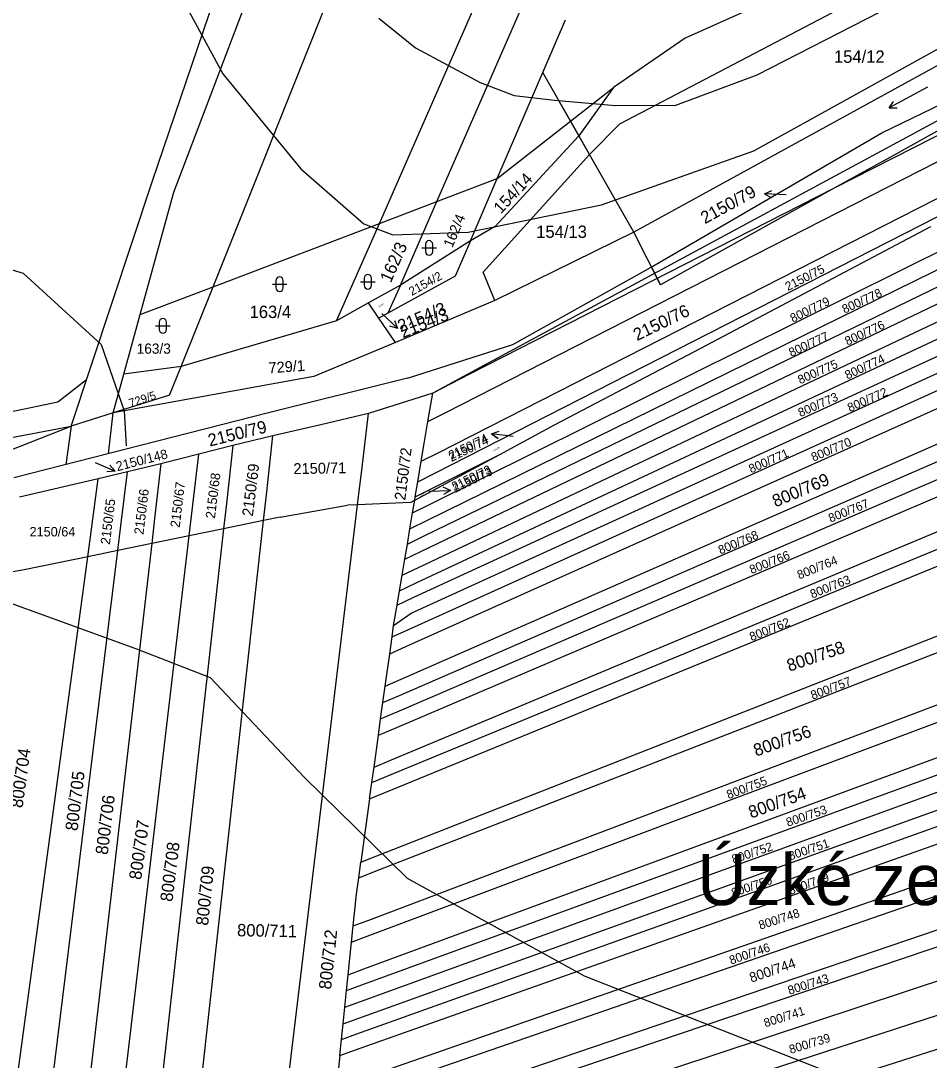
# Model space of a CAD drawing. Extents: x -555860 to -552701, y -1187050 to -1182291.
# Drawn here: x -554861.7 to -554737.1, y -1185587.5 to -1185444.8 of the extents above; entities that cross this region are included whole.
import ezdxf

# ---------------------------------------------------------------- set-up
doc = ezdxf.new("R2010")
doc.units = 0
for name, color, linetype in [('LEG_2b', 7, 'Continuous'), ('Level 16', 7, 'Continuous'), ('Level 25', 7, 'Continuous'), ('Level 32', 7, 'Continuous'), ('Level 40', 7, 'Continuous'), ('Level 41', 7, 'Continuous'), ('navrh_BV', 7, 'Continuous'), ('Parcelní čísla', 7, 'Continuous'), ('Poz předměty', 7, 'Continuous'), ('stav_BV', 7, 'Continuous')]:
    doc.layers.add(name, color=color, linetype=linetype)

msp = doc.modelspace()

# ---------------------------------------------------------------- linework, layer by layer
at = {"layer": 'Level 16'}
for p, q in [((-554759.67, -1185468.55), (-554758.65, -1185468.09)), ((-554756.67, -1185468.68), (-554759.67, -1185468.55)), ((-554759.67, -1185468.55), (-554758.69, -1185469.09)), ((-554812.17, -1185484.98), (-554809.97, -1185487.02)), ((-554809.97, -1185487.02), (-554810.36, -1185485.97)), ((-554809.97, -1185487.02), (-554811.04, -1185486.71)), ((-554797.1, -1185501.49), (-554796.05, -1185501.1)), ((-554794.12, -1185501.83), (-554797.1, -1185501.49)), ((-554797.1, -1185501.49), (-554796.17, -1185502.1)), ((-554851.5, -1185505.42), (-554848.75, -1185506.62)), ((-554848.75, -1185506.62), (-554849.86, -1185506.68)), ((-554848.75, -1185506.62), (-554849.47, -1185505.76)), ((-554805.71, -1185509.35), (-554802.71, -1185509.25)), ((-554802.71, -1185509.25), (-554803.73, -1185508.78)), ((-554802.71, -1185509.25), (-554803.69, -1185509.78))]:
    msp.add_line(p, q, dxfattribs=at)
at = {"layer": 'Level 25'}
for p, q in [((-554737.28, -1185453.91), (-554742.56, -1185456.75)), ((-554742.56, -1185456.75), (-554741.94, -1185455.85)), ((-554742.56, -1185456.75), (-554741.46, -1185456.73)), ((-554806.67, -1185475.96), (-554804.67, -1185475.96)), ((-554806.17, -1185475.46), (-554806.17, -1185476.46)), ((-554805.17, -1185476.46), (-554805.17, -1185475.46)), ((-554827.17, -1185480.93), (-554825.17, -1185480.93)), ((-554826.67, -1185480.43), (-554826.67, -1185481.43)), ((-554825.67, -1185481.43), (-554825.67, -1185480.43)), ((-554815.08, -1185480.6), (-554813.08, -1185480.6)), ((-554814.58, -1185480.1), (-554814.58, -1185481.1)), ((-554813.58, -1185481.1), (-554813.58, -1185480.1)), ((-554843.2, -1185486.65), (-554841.2, -1185486.65)), ((-554842.7, -1185486.15), (-554842.7, -1185487.15)), ((-554841.7, -1185487.15), (-554841.7, -1185486.15))]:
    msp.add_line(p, q, dxfattribs=at)
for centre, start, end in [((-554805.67, -1185475.46), 0, 180), ((-554805.67, -1185476.46), 180, 359.9879), ((-554826.17, -1185480.43), 0, 180), ((-554814.08, -1185480.1), 0, 180), ((-554826.17, -1185481.43), 180, 359.9879), ((-554814.08, -1185481.1), 180, 359.9879), ((-554842.2, -1185486.15), 0, 180), ((-554842.2, -1185487.15), 180, 359.9879)]:
    msp.add_arc(centre, 0.5, start, end, dxfattribs=at)
at = {"layer": 'Level 32'}
msp.add_lwpolyline([(-554698.05, -1185438.6), (-554714.96, -1185448.24), (-554741.93, -1185463.25), (-554750.17, -1185467.82), (-554773.94, -1185481.01), (-554777.58, -1185473.79), (-554783.65, -1185463.15), (-554790.07, -1185451.89), (-554786.97, -1185444.66)], dxfattribs=at)
at = {"layer": 'Level 40'}
msp.add_lwpolyline([(-554812.57, -1185444.44), (-554807.55, -1185448.5), (-554798.66, -1185453.23), (-554793.98, -1185455.02), (-554788.44, -1185455.68), (-554780.08, -1185456.4), (-554771.8, -1185456.38), (-554760.66, -1185452.22), (-554741.91, -1185442.57)], dxfattribs=at)
at = {"layer": 'Level 41'}
for points in [[(-554871.41, -1185304.71), (-554871.04, -1185319.22), (-554873.45, -1185336.56), (-554879.64, -1185354.6), (-554880.53, -1185368.5), (-554877.6, -1185382.58), (-554873.3, -1185396.32), (-554862.7, -1185410.01), (-554853.22, -1185420.99), (-554839.21, -1185442.35), (-554833.95, -1185452.05), (-554823.27, -1185465.09), (-554814.61, -1185472.65), (-554810.64, -1185474.15), (-554800.31, -1185473.8), (-554782, -1185470.03), (-554761.13, -1185462.61), (-554710.48, -1185434.53), (-554672.53, -1185409.41), (-554665.16, -1185406.66), (-554661.47, -1185407.95)], [(-554885.26, -1185472.28), (-554861.37, -1185479.43), (-554850.64, -1185489.22), (-554847.52, -1185498.32), (-554847.22, -1185503.13)], [(-554861.82, -1185736.58), (-554855.72, -1185724.37), (-554848.78, -1185706.63), (-554841.57, -1185691.1), (-554835.75, -1185682.22), (-554827.15, -1185673.63), (-554815.23, -1185666.28), (-554803.02, -1185664.5), (-554780.56, -1185665.98), (-554758.45, -1185666.46), (-554743.41, -1185662.98), (-554728.4, -1185655.15), (-554719.09, -1185646.7), (-554716.06, -1185638.41), (-554716.6, -1185624.9), (-554722.1, -1185608.2), (-554732.26, -1185596.23), (-554752.76, -1185588.36), (-554784.35, -1185575.91), (-554808.64, -1185562.53), (-554822.82, -1185548.58), (-554835.67, -1185534.96), (-554845.75, -1185531.02), (-554875.77, -1185520.13)]]:
    msp.add_lwpolyline(points, dxfattribs=at)
at = {"layer": 'navrh_BV'}
for p, q in [((-554840.69, -1185468.29), (-554825.35, -1185427.87)), ((-554779.51, -1185458.92), (-554718.55, -1185426.98)), ((-554843.68, -1185466.9), (-554831.78, -1185431.89)), ((-554835.3, -1185481.29), (-554815.64, -1185432.15)), ((-554689.29, -1185433.35), (-554800.95, -1185493.61)), ((-554683.08, -1185433.59), (-554750.17, -1185467.82)), ((-554803.46, -1185498.58), (-554683.26, -1185437.19)), ((-554711.78, -1185437.68), (-554777.58, -1185473.79)), ((-554812.49, -1185472.6), (-554798.15, -1185439.85)), ((-554804.61, -1185469.6), (-554792.66, -1185442.27)), ((-554759.77, -1185442.35), (-554770.52, -1185447.18)), ((-554804.42, -1185504.06), (-554683.68, -1185442.47)), ((-554796.32, -1185466.44), (-554786.97, -1185444.66)), ((-554743.55, -1185460.15), (-554715.8, -1185446.65)), ((-554770.52, -1185447.18), (-554780.36, -1185453.92)), ((-554805.59, -1185511.17), (-554684.18, -1185450.82)), ((-554805.87, -1185513.31), (-554684.41, -1185453.64)), ((-554796.32, -1185466.44), (-554780.36, -1185453.92)), ((-554780.36, -1185453.92), (-554785.14, -1185460.55)), ((-554806.33, -1185515.48), (-554684.4, -1185456.26)), ((-554806.69, -1185517.56), (-554684.71, -1185459.08)), ((-554783.65, -1185463.15), (-554779.51, -1185458.92)), ((-554785.14, -1185460.55), (-554796.62, -1185473)), ((-554775.19, -1185478.62), (-554743.55, -1185460.15)), ((-554807.1, -1185519.8), (-554684.86, -1185461.9)), ((-554804.88, -1185506.88), (-554718.03, -1185462.53)), ((-554798.25, -1185479.27), (-554783.65, -1185463.15)), ((-554777.58, -1185473.79), (-554783.65, -1185463.15)), ((-554807.42, -1185521.93), (-554685.04, -1185464.6)), ((-554804.61, -1185469.6), (-554796.32, -1185466.44)), ((-554799.99, -1185474.98), (-554796.32, -1185466.44)), ((-554854.76, -1185500.41), (-554843.68, -1185466.9)), ((-554807.75, -1185523.9), (-554685.28, -1185467.47)), ((-554750.17, -1185467.82), (-554800.1, -1185493.3)), ((-554845.3, -1185485.1), (-554840.69, -1185468.29)), ((-554812.49, -1185472.6), (-554804.61, -1185469.6)), ((-554809.61, -1185481.05), (-554804.61, -1185469.6)), ((-554808.11, -1185526.08), (-554685.37, -1185470.07)), ((-554835.3, -1185481.29), (-554812.49, -1185472.6)), ((-554818.35, -1185485.97), (-554812.49, -1185472.6)), ((-554808.59, -1185528.38), (-554685.58, -1185472.75)), ((-554796.62, -1185473), (-554799.99, -1185474.98)), ((-554777.58, -1185473.79), (-554796.64, -1185483.19)), ((-554769.17, -1185490.14), (-554736.83, -1185473)), ((-554799.99, -1185474.98), (-554809.61, -1185481.05)), ((-554799.99, -1185474.98), (-554802.08, -1185479.85)), ((-554808.84, -1185530.68), (-554685.72, -1185475.49)), ((-554796.64, -1185483.19), (-554798.25, -1185479.27)), ((-554794.19, -1185489.23), (-554775.19, -1185478.62)), ((-554802.08, -1185479.85), (-554811.31, -1185484.93)), ((-554845.3, -1185485.1), (-554835.3, -1185481.29)), ((-554839.68, -1185492.24), (-554835.3, -1185481.29)), ((-554809.61, -1185481.05), (-554813.97, -1185483.5)), ((-554809.61, -1185481.05), (-554811.31, -1185484.93)), ((-554809.49, -1185535.15), (-554686.09, -1185480.99)), ((-554813.97, -1185483.5), (-554818.35, -1185485.97)), ((-554812.55, -1185485.59), (-554813.97, -1185483.5)), ((-554796.64, -1185483.19), (-554810.27, -1185488.94)), ((-554809.74, -1185537.39), (-554686.25, -1185483.67)), ((-554847.55, -1185493.29), (-554845.3, -1185485.1)), ((-554811.31, -1185484.93), (-554812.55, -1185485.59)), ((-554818.35, -1185485.97), (-554839.68, -1185492.24)), ((-554810.27, -1185488.94), (-554812.55, -1185485.59)), ((-554810.05, -1185539.64), (-554686.47, -1185486.44)), ((-554810.27, -1185488.94), (-554821.46, -1185493.59)), ((-554810.34, -1185541.87), (-554686.86, -1185489.13)), ((-554808.63, -1185493.83), (-554794.19, -1185489.23)), ((-554788.44, -1185500.22), (-554769.17, -1185490.14)), ((-554839.68, -1185492.24), (-554847.55, -1185493.29)), ((-554841.26, -1185496.19), (-554839.68, -1185492.24)), ((-554849, -1185498.59), (-554847.55, -1185493.29)), ((-554821.46, -1185493.59), (-554849, -1185498.59)), ((-554800.1, -1185493.3), (-554805.16, -1185495.88)), ((-554800.95, -1185493.61), (-554805.16, -1185495.88)), ((-554808.63, -1185493.83), (-554827.71, -1185498.61)), ((-554811.04, -1185546.3), (-554687.16, -1185494.46)), ((-554841.26, -1185496.19), (-554849, -1185498.59)), ((-554805.16, -1185495.88), (-554813.98, -1185498.7)), ((-554805.82, -1185499.78), (-554805.16, -1185495.88)), ((-554811.32, -1185548.44), (-554687.2, -1185497.19)), ((-554827.71, -1185498.61), (-554862.64, -1185507.52)), ((-554849, -1185498.59), (-554854.76, -1185500.41)), ((-554813.98, -1185498.7), (-554820.53, -1185500.22)), ((-554814.82, -1185505.68), (-554813.98, -1185498.7)), ((-554805.82, -1185499.78), (-554803.46, -1185498.58)), ((-554888.64, -1185506.89), (-554854.76, -1185500.41)), ((-554870.31, -1185506.52), (-554854.76, -1185500.41)), ((-554820.53, -1185500.22), (-554827.09, -1185501.73)), ((-554811.61, -1185550.67), (-554687.34, -1185499.7)), ((-554806.33, -1185502.81), (-554805.82, -1185499.78)), ((-554795.98, -1185504.29), (-554788.44, -1185500.22)), ((-554827.09, -1185501.73), (-554832.59, -1185503.07)), ((-554827.99, -1185509.86), (-554827.09, -1185501.73)), ((-554832.59, -1185503.07), (-554837.27, -1185504.28)), ((-554832.59, -1185503.07), (-554833.48, -1185511.02)), ((-554806.74, -1185505.24), (-554806.33, -1185502.81)), ((-554837.27, -1185504.28), (-554842.45, -1185505.61)), ((-554838.18, -1185512.02), (-554837.27, -1185504.28)), ((-554807.64, -1185510.59), (-554795.98, -1185504.29)), ((-554806.74, -1185505.24), (-554804.42, -1185504.06)), ((-554805.22, -1185508.95), (-554795.98, -1185504.29)), ((-554842.45, -1185505.61), (-554847.03, -1185506.69)), ((-554842.45, -1185505.61), (-554843.32, -1185513.1)), ((-554815.48, -1185511.21), (-554814.82, -1185505.68)), ((-554807.21, -1185508.07), (-554806.74, -1185505.24)), ((-554851.05, -1185507.63), (-554861.88, -1185510.16)), ((-554852.04, -1185514.94), (-554851.05, -1185507.63)), ((-554847.03, -1185506.69), (-554851.05, -1185507.63)), ((-554847.94, -1185514.08), (-554847.03, -1185506.69)), ((-554807.56, -1185510.13), (-554807.21, -1185508.07)), ((-554807.21, -1185508.07), (-554804.88, -1185506.88)), ((-554807.56, -1185510.13), (-554805.22, -1185508.95)), ((-554828.38, -1185513.39), (-554827.99, -1185509.86)), ((-554808.2, -1185510.89), (-554815.48, -1185511.21)), ((-554812.84, -1185559.41), (-554687.93, -1185510.33)), ((-554808.2, -1185510.89), (-554807.64, -1185510.59)), ((-554807.93, -1185512.34), (-554807.64, -1185510.59)), ((-554807.64, -1185510.59), (-554807.56, -1185510.13)), ((-554838.59, -1185515.49), (-554838.18, -1185512.02)), ((-554833.48, -1185511.02), (-554833.87, -1185514.52)), ((-554830.89, -1185639.42), (-554815.48, -1185511.21)), ((-554826.08, -1185512.92), (-554816.86, -1185511.27)), ((-554815.48, -1185511.21), (-554816.86, -1185511.27)), ((-554808.3, -1185514.5), (-554807.93, -1185512.34)), ((-554807.93, -1185512.34), (-554805.59, -1185511.17)), ((-554843.32, -1185513.1), (-554843.72, -1185516.54)), ((-554840.78, -1185625.57), (-554828.38, -1185513.39)), ((-554828.38, -1185513.39), (-554833.87, -1185514.52)), ((-554826.08, -1185512.92), (-554828.38, -1185513.39)), ((-554813.16, -1185561.56), (-554688.2, -1185512.92)), ((-554808.3, -1185514.5), (-554805.87, -1185513.31)), ((-554852.5, -1185518.35), (-554852.04, -1185514.94)), ((-554848.36, -1185517.5), (-554847.94, -1185514.08)), ((-554833.87, -1185514.52), (-554845.5, -1185618.65)), ((-554833.87, -1185514.52), (-554838.59, -1185515.49)), ((-554808.65, -1185516.61), (-554808.3, -1185514.5)), ((-554843.72, -1185516.54), (-554854.21, -1185607.15)), ((-554850.07, -1185612.7), (-554838.59, -1185515.49)), ((-554843.72, -1185516.54), (-554848.36, -1185517.5)), ((-554838.59, -1185515.49), (-554843.72, -1185516.54)), ((-554809, -1185518.66), (-554808.65, -1185516.61)), ((-554808.65, -1185516.61), (-554806.33, -1185515.48)), ((-554858.64, -1185601), (-554848.36, -1185517.5)), ((-554848.36, -1185517.5), (-554852.5, -1185518.35)), ((-554809, -1185518.66), (-554806.69, -1185517.56)), ((-554862.87, -1185595.23), (-554852.5, -1185518.35)), ((-554852.5, -1185518.35), (-554861.2, -1185520.14)), ((-554809.37, -1185520.88), (-554809, -1185518.66)), ((-554861.2, -1185520.14), (-554863.27, -1185520.5)), ((-554813.94, -1185568.21), (-554688.68, -1185520.72)), ((-554809.73, -1185523.01), (-554809.37, -1185520.88)), ((-554809.37, -1185520.88), (-554807.1, -1185519.8)), ((-554809.73, -1185523.01), (-554807.42, -1185521.93)), ((-554814.15, -1185570.44), (-554688.73, -1185523.33)), ((-554810.06, -1185524.97), (-554809.73, -1185523.01)), ((-554810.53, -1185527.79), (-554810.06, -1185524.97)), ((-554810.06, -1185524.97), (-554807.75, -1185523.9)), ((-554810.53, -1185527.79), (-554808.11, -1185526.08)), ((-554810.75, -1185529.35), (-554810.53, -1185527.79)), ((-554814.61, -1185574.92), (-554689, -1185528.59)), ((-554811.07, -1185531.68), (-554810.75, -1185529.35)), ((-554810.75, -1185529.35), (-554808.59, -1185528.38)), ((-554811.07, -1185531.68), (-554808.84, -1185530.68)), ((-554814.87, -1185577.12), (-554689.27, -1185531.19)), ((-554811.69, -1185536.12), (-554811.07, -1185531.68)), ((-554815.07, -1185579.4), (-554689.4, -1185533.75)), ((-554811.69, -1185536.12), (-554809.49, -1185535.15)), ((-554815.32, -1185581.68), (-554689.69, -1185536.43)), ((-554812, -1185538.37), (-554811.69, -1185536.12)), ((-554812, -1185538.37), (-554809.74, -1185537.39)), ((-554815.56, -1185583.84), (-554689.79, -1185538.86)), ((-554812.31, -1185540.61), (-554812, -1185538.37)), ((-554812.62, -1185542.84), (-554812.31, -1185540.61)), ((-554812.31, -1185540.61), (-554810.05, -1185539.64)), ((-554815.74, -1185586.04), (-554689.98, -1185541.48)), ((-554812.62, -1185542.84), (-554810.34, -1185541.87)), ((-554813.22, -1185547.21), (-554812.62, -1185542.84)), ((-554816.17, -1185590.43), (-554690.31, -1185546.54)), ((-554813.22, -1185547.21), (-554811.04, -1185546.3)), ((-554813.52, -1185549.35), (-554813.22, -1185547.21)), ((-554816.44, -1185592.67), (-554690.44, -1185549.09)), ((-554813.83, -1185551.58), (-554813.52, -1185549.35)), ((-554813.52, -1185549.35), (-554811.32, -1185548.44)), ((-554813.83, -1185551.58), (-554811.61, -1185550.67)), ((-554813.83, -1185551.58), (-554815.03, -1185560.26)), ((-554816.83, -1185597.07), (-554690.73, -1185554.14)), ((-554817.1, -1185599.28), (-554690.77, -1185556.59)), ((-554815.03, -1185560.26), (-554812.84, -1185559.41)), ((-554815.32, -1185562.41), (-554815.03, -1185560.26)), ((-554817.52, -1185603.53), (-554691.18, -1185561.79)), ((-554815.32, -1185562.41), (-554813.16, -1185561.56)), ((-554815.63, -1185564.64), (-554815.32, -1185562.41)), ((-554816.08, -1185569.02), (-554815.63, -1185564.64)), ((-554817.91, -1185607.94), (-554691.43, -1185566.77)), ((-554816.31, -1185571.25), (-554816.08, -1185569.02)), ((-554816.08, -1185569.02), (-554813.94, -1185568.21)), ((-554816.31, -1185571.25), (-554814.15, -1185570.44)), ((-554818.27, -1185612.23), (-554691.76, -1185571.79)), ((-554816.77, -1185575.72), (-554816.31, -1185571.25)), ((-554816.77, -1185575.72), (-554814.61, -1185574.92)), ((-554816.99, -1185577.89), (-554816.77, -1185575.72)), ((-554817.23, -1185580.18), (-554816.99, -1185577.89)), ((-554816.99, -1185577.89), (-554814.87, -1185577.12)), ((-554817.23, -1185580.18), (-554815.07, -1185579.4)), ((-554817.46, -1185582.45), (-554817.23, -1185580.18)), ((-554817.46, -1185582.45), (-554815.32, -1185581.68)), ((-554817.68, -1185584.59), (-554817.46, -1185582.45)), ((-554817.91, -1185586.81), (-554817.68, -1185584.59)), ((-554817.68, -1185584.59), (-554815.56, -1185583.84)), ((-554817.91, -1185586.81), (-554815.74, -1185586.04)), ((-554817.91, -1185586.81), (-554818.36, -1185591.2))]:
    msp.add_line(p, q, dxfattribs=at)
at = {"layer": 'Poz předměty'}
for points in [[(-554783.65, -1185463.15), (-554785.14, -1185460.54), (-554790.07, -1185451.89)], [(-554775.16, -1185478.6), (-554773.94, -1185481.01)], [(-555101.59, -1185540.83), (-555099.07, -1185543.16), (-555038.97, -1185532.52), (-554974.74, -1185520.88), (-554917.32, -1185509.78), (-554856.6, -1185497.07), (-554852.65, -1185494.03)], [(-554849.65, -1185504.21), (-554849, -1185498.59)], [(-554854.76, -1185500.41), (-554855.48, -1185505.69)]]:
    msp.add_lwpolyline(points, dxfattribs=at)
at = {"layer": 'stav_BV'}
for p, q in [((-554812.17, -1185484.98), (-554809.97, -1185487.03)), ((-554809.97, -1185487.03), (-554810.37, -1185485.98)), ((-554809.97, -1185487.03), (-554811.05, -1185486.71)), ((-554797.1, -1185501.46), (-554796.04, -1185501.09)), ((-554794.12, -1185501.83), (-554797.1, -1185501.46)), ((-554797.1, -1185501.46), (-554796.17, -1185502.08)), ((-554805.71, -1185509.35), (-554802.71, -1185509.25)), ((-554802.71, -1185509.25), (-554803.73, -1185508.78)), ((-554802.71, -1185509.25), (-554803.69, -1185509.78))]:
    msp.add_line(p, q, dxfattribs=at)

# ---------------------------------------------------------------- texts
at = {"layer": 'LEG_2b'}
for s, height, p in [('154/12', 1.7, (-554750.12, -1185450.55)), ('154/13', 1.7, (-554790.97, -1185474.58)), ('163/4', 1.7, (-554830.29, -1185485.58)), ('163/3', 1.4, (-554845.78, -1185490.48)), ('2150/64', 1.3, (-554860.48, -1185515.56))]:
    msp.add_text(s, height=height, dxfattribs=at).set_placement(p)
for s, height, rotation, p in [('154/14', 1.6, 47, (-554795.81, -1185471.37)), ('162/4', 1.4, 67, (-554802.48, -1185476.02)), ('162/3', 1.7, 66, (-554810.92, -1185480.85)), ('2154/2', 1.2, 29, (-554808.04, -1185482.56)), ('2150/75', 1.2, 27, (-554756.44, -1185481.88)), ('800/778', 1.2, 25, (-554748.67, -1185484.99)), ('2154/3', 0.2, 29, (-554812.55, -1185484.11)), ('2150/76', 1.7, 26, (-554777.14, -1185488.76)), ('800/779', 1.2, 26, (-554755.77, -1185486.23)), ('2154/3', 1.7, 22, (-554809.25, -1185488.37)), ('800/776', 1.2, 25, (-554748.28, -1185489.38)), ('800/777', 1.2, 25, (-554755.98, -1185490.94)), ('800/774', 1.2, 25, (-554748.28, -1185494.04)), ('729/1', 1.5, 4, (-554827.65, -1185493.18)), ('800/775', 1.2, 24, (-554754.76, -1185494.68)), ('800/772', 1.2, 24, (-554747.94, -1185498.51)), ('729/5', 1.139, 18, (-554846.64, -1185497.84)), ('800/773', 1.2, 24, (-554754.72, -1185499.19)), ('2150/79', 1.7, 14, (-554835.77, -1185503.24)), ('2150/74', 1.2, 26, (-554802.59, -1185505.34)), ('800/770', 1.2, 23, (-554752.94, -1185505.3)), ('2150/72', 1.5, 83, (-554808.93, -1185510.66)), ('2150/74', 0.2, 28, (-554796.83, -1185503.9)), ('800/771', 1.2, 24, (-554761.49, -1185506.91)), ('2150/69', 1.5, 83, (-554829.84, -1185512.86)), ('2150/71', 1.5, 1, (-554824.27, -1185507.01)), ('2150/73', 1.2, 26, (-554802.07, -1185509.59)), ('2150/68', 1.3, 83, (-554835.05, -1185513.15)), ('800/769', 1.7, 23, (-554758.14, -1185511.58)), ('2150/66', 1.3, 83, (-554844.86, -1185515.36)), ('2150/67', 1.3, 83, (-554839.89, -1185514.39)), ('2150/73', 0.2, 29, (-554806.91, -1185510.1)), ('2150/65', 1.3, 83, (-554849.46, -1185516.72)), ('800/767', 1.2, 22, (-554750.59, -1185513.67)), ('800/768', 1.2, 23, (-554765.69, -1185518.05)), ('800/766', 1.2, 22, (-554761.42, -1185520.74)), ('800/764', 1.2, 22, (-554754.88, -1185521.46)), ('800/763', 1.2, 22, (-554753.1, -1185524.1)), ('800/762', 1.2, 22, (-554761.42, -1185529.95)), ('800/758', 1.7, 19, (-554756.24, -1185534.14)), ('800/757', 1.2, 21, (-554753.04, -1185537.98)), ('800/756', 1.7, 20, (-554760.79, -1185545.79)), ('800/704', 1.7, 82, (-554861.45, -1185552.9)), ('800/705', 1.7, 83, (-554853.9, -1185556.04)), ('800/755', 1.2, 21, (-554764.58, -1185551.63)), ('800/754', 1.7, 20, (-554761.48, -1185554.29)), ('800/706', 1.7, 83, (-554849.76, -1185559.32)), ('800/753', 1.2, 19, (-554756.44, -1185555.42)), ('800/707', 1.7, 82, (-554845.17, -1185562.76)), ('800/708', 1.7, 83, (-554840.88, -1185565.76)), ('800/752', 1.2, 19, (-554763.9, -1185560.49)), ('800/751', 1.2, 19, (-554756.13, -1185560.04)), ('800/709', 1.7, 84, (-554835.99, -1185569.04)), ('800/750', 1.2, 19, (-554763.96, -1185565.09)), ('800/749', 1.2, 20, (-554756.11, -1185564.78)), ('800/748', 1.2, 18, (-554760.23, -1185569.54)), ('800/711', 1.7, 359, (-554832.02, -1185570.44)), ('800/712', 1.7, 84, (-554819.12, -1185577.8)), ('800/746', 1.2, 19, (-554764.24, -1185574.35)), ('800/744', 1.36, 19, (-554761.45, -1185576.82)), ('800/743', 1.2, 18, (-554756.23, -1185578.49)), ('800/741', 1.2, 18, (-554759.52, -1185582.96)), ('800/739', 1.2, 17, (-554756.06, -1185586.59))]:
    msp.add_text(s, height=height, rotation=rotation, dxfattribs=at).set_placement(p)
at = {"layer": 'Level 16'}
for s, height, rotation, p in [('2150/79', 1.7, 28.8, (-554767.83, -1185472.72)), ('2154/3', 1.7, 22.5, (-554809.56, -1185487.56)), ('2150/74', 1.2, 26.1, (-554802.64, -1185505.03)), ('2150/148', 1.3, 14.4, (-554848.44, -1185506.61)), ('2150/73', 1.2, 26.1, (-554802.21, -1185509.32))]:
    msp.add_text(s, height=height, rotation=rotation, dxfattribs=at).set_placement(p)
at = {"layer": 'Parcelní čísla'}
msp.add_text('Úzké zelnice', height=7, dxfattribs=at).set_placement((-554768.86, -1185566.16))

doc.saveas('drawing.dxf')
